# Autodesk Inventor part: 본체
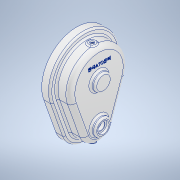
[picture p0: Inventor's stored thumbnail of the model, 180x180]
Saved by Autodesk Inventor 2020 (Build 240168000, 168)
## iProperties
Created: 2024-05
Part Number: 본체
Material: 알루미늄 6061
Document SubType Name: Modeling
Designer: oem
Density: 2.7 g/cm^3
Appearance: 알루미늄 - 평지
Author: oem
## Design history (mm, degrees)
sketch "스케치7"
  geometry: L1 (0, 0)-(-69, 0); L2 (-20.667, 58.454)-(-82, 36.77); L3 (-17, 48.083)-(-78.333, 26.399); L4 (-17, -48.083)-(-78.333, -26.399); L5 (-20.667, -58.454)-(-82, -36.77); A1 r 62 centre (0, 0) between (-20.667, 58.454) and (-20.667, -58.454); A2 r 51 centre (0, 0) between (-17, 48.083) and (-17, -48.083); A3 r 39 centre (-69, 0) between (-82, 36.77) and (-82, -36.77); A4 r 28 centre (-69, 0) between (-78.333, 26.399) and (-78.333, -26.399); 1 further point
  constraints: 10 end point, 8 point on circle, 7 tangent, 4 centre point, 4 coincident, 1 horizontal, 1 parallel
  dimensions: "d26" = 124 diameter of A1; "d27" = 102 diameter of A2; "d28" = 69 distance of L1.start L1.end; "d29" = 78 diameter of A3; "d30" = 56 diameter of A4
extrude "돌출5" new body sketch "스케치7" distance "d31" = 15; taper "d32" = 0 deg
extrude "돌출6" join sketch "스케치7" distance "d33" = 40; taper "d34" = 0 deg
sketch "스케치8"
  geometry: C1 r 15 at (0, 0); C2 r 15 at (0, -69); A1 r 28 centre (0, -69) between (-26.399, -78.333) and (26.399, -78.333) reference; A2 r 51 centre (0, 0) between (48.083, -17) and (-48.083, -17) reference
  constraints: 2 centre point, 2 coincident
  dimensions: "d35" = 30 diameter of C1; "d36" = 30 diameter of C2
extrude "돌출7" join sketch "스케치8" distance "d37" = 8; taper "d38" = 0 deg
feature "쉘1" dims "d40" = 5
node "작업 평면4"
fillet "모깎기3" dims "d58" = 8
fillet "모깎기5" dims "d60" = 3
node "작업 평면6"
sketch "스케치16"
  geometry: C1 r 6 at (13, 0) reference; 1 further point
extrude "돌출9" join sketch "스케치16" distance "d61" = 3; taper "d63" = 0 deg; dims "d62" = 1.5, "d64" = 0
sketch "스케치17"
  geometry: C1 r 6 at (0, 0) reference; 2 further points
  constraints: 1 coincident
hole "구멍2" sketch "스케치17" at (0, 0) diameter "d65" = 5.1881; stored, may be unused: countersink angle "d69" = 90 deg, drill point angle "d71" = 0 deg; dims "d66" = 5, "d67" = 7, "d68" = 2, "d70" = 9
node "작업 평면7"
sketch "스케치18"
  geometry: C1 r 6 at (28, 0) reference; 1 further point
extrude "돌출10" join sketch "스케치18" distance "d72" = 3; taper "d74" = 0 deg; dims "d73" = 1.5, "d75" = 0
sketch "스케치19"
  geometry: C1 r 6 at (0, 0) reference; 2 further points
  constraints: 1 coincident
hole "구멍3" sketch "스케치19" at (0, 0) diameter "d76" = 5.1881; stored, may be unused: countersink angle "d80" = 90 deg, drill point angle "d82" = 0 deg; dims "d77" = 5, "d78" = 7, "d79" = 2, "d81" = 9
sketch "스케치20"
  geometry: C1 r 14 at (0, 0); C2 r 14 at (0, -69); A1 r 46 centre (0, 0) between (43.369, -15.333) and (-43.369, -15.333) reference; A2 r 23 centre (0, -69) between (-21.685, -76.667) and (21.685, -76.667) reference
  constraints: 2 centre point, 2 coincident
  dimensions: "d83" = 28 diameter of C1; "d85" = 28 diameter of C2
extrude "돌출11" join sketch "스케치20" distance "d86" = 10; taper "d87" = 0 deg
sketch "스케치21"
  geometry: C1 r 14 at (0, 0) reference; 2 further points
  constraints: 1 coincident
hole "구멍4" sketch "스케치21" at (0, 0) diameter "d88" = 14; stored, may be unused: countersink angle "d92" = 90 deg, drill point angle "d94" = 118 deg; dims "d89" = 14, "d90" = 7, "d91" = 2, "d93" = 5
sketch "스케치22"
  geometry: C1 r 12 at (0, 0) reference; 2 further points
  constraints: 1 coincident
hole "구멍5" sketch "스케치22" at (0, 0) diameter "d95" = 14; stored, may be unused: countersink angle "d99" = 90 deg, drill point angle "d101" = 118 deg; dims "d96" = 14, "d97" = 20, "d98" = 4.2, "d100" = 5
fillet "모깎기6" dims "d102" = 3
sketch "스케치28"
  geometry: L1 (0, 0)-(0, 51.794)
  constraints: 2 end point, 1 vertical
hole "구멍7" sketch "스케치28" at (0, 51.794) diameter "d116" = 3.242; stored, may be unused: countersink angle "d120" = 90 deg, drill point angle "d122" = 118 deg; dims "d117" = 3, "d118" = 20, "d119" = 4.2, "d121" = 4
fillet "모깎기7" dims "d123" = 3
sketch "스케치29"
  geometry: L1 (0, 0)-(0, -34); L2 (0, -34)-(41.952, -34); L3 (0, -34)-(-41.952, -34); C1 r 7 at (0, 0) reference
  constraints: 6 end point, 1 horizontal, 1 perpendicular, 1 vertical
  dimensions: "d127" = 34 distance of L1.start L1.end
hole "구멍8" sketch "스케치29" at (-41.952, -34), (41.952, -34) diameter "d128" = 3.242; stored, may be unused: countersink angle "d132" = 90 deg, drill point angle "d134" = 118 deg; dims "d129" = 3, "d130" = 20, "d131" = 4.2, "d133" = 4
sketch "스케치31"
  geometry: 1 further point
  constraints: 1 other
feature "엠보싱1" sketch "스케치31" dims "d35" = 30, "d142" = 0.5, "d143" = 0
node "솔리드3"
pattern_circular "원형 패턴1" dims angle "d125" = 90 deg
mirror "미러1"
feature "A9D066F2-1C7D-4E18-AEED-F7BC21143FA4" dims "d65" = 5.1881, "d66" = 5, "d67" = 7, "d68" = 2, "d69" = 90 deg, "d70" = 9, "d71" = 0
other parameters: "d44" = 59
